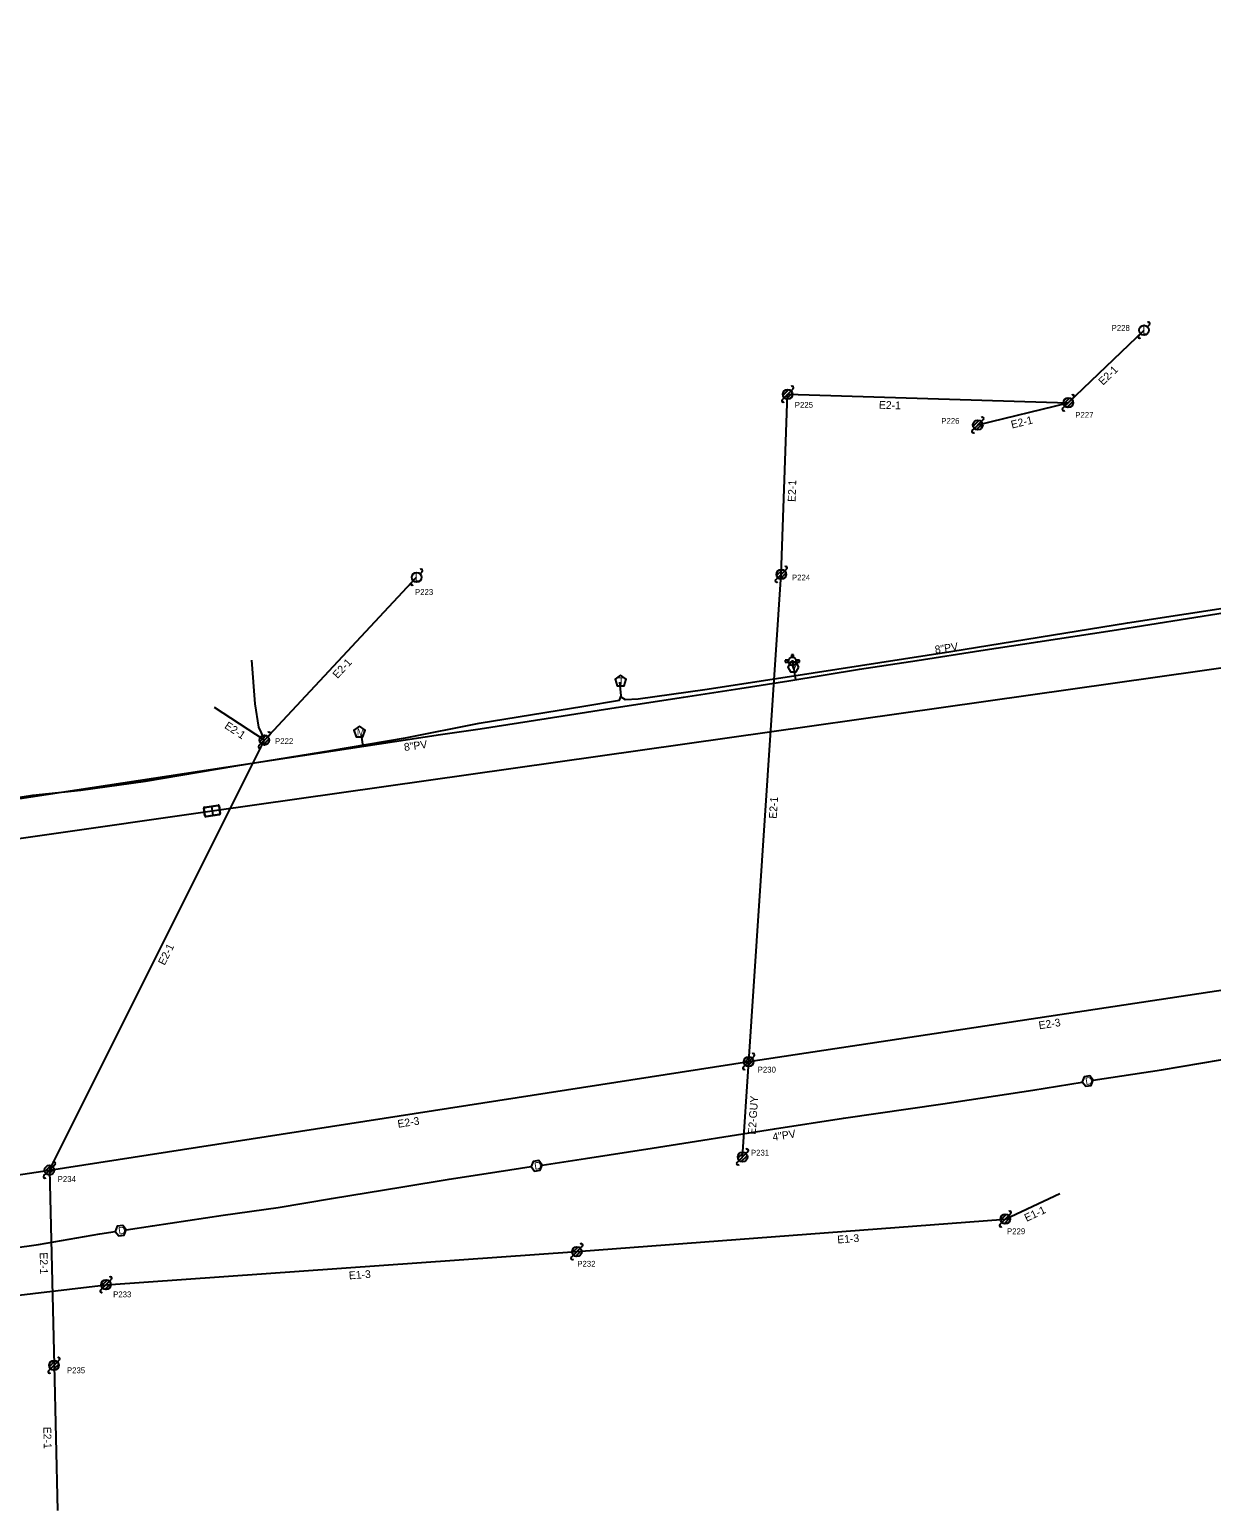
# Model space of a CAD drawing. Extents: x 1614474 to 1865144, y 1098877 to 1212550.
# Drawn here: x 1776816 to 1777423, y 1179838 to 1180599 of the extents above; entities that cross this region are included whole.
import ezdxf

# ---------------------------------------------------------------- set-up
doc = ezdxf.new("R2010")
doc.units = 0
for name, color, linetype in [('BFUSER_DUCTENCLOSURE', 7, 'Continuous'), ('BFUSER_FIBERSPAN', 7, 'Continuous'), ('RD_EX_SU_Elec', 7, 'Continuous'), ('RD_EX_SU_H2O', 7, 'Continuous'), ('RD_EX_SU_Ovhd', 7, 'Continuous'), ('RD_EX_SU_Pole', 7, 'Continuous'), ('RD_EX_SU_Telecom', 7, 'Continuous'), ('RD_EX_SU_TX_H2O', 7, 'Continuous'), ('RD_EX_SU_TX_Pole', 7, 'Continuous')]:
    doc.layers.add(name, color=color, linetype=linetype)

# ---------------------------------------------------------------- blocks, each defined once
blk = doc.blocks.new('SUE_PP')
at = {"layer": 'RD_EX_SU_Pole'}
for p, q in [((-2.41, -0.65), (0.65, 2.41)), ((-1.77, -1.77), (1.77, 1.77)), ((-0.65, -2.41), (2.41, 0.65)), ((1.77, 1.77), (2.83, 2.83)), ((-2.83, -2.83), (-1.77, -1.77))]:
    blk.add_line(p, q, dxfattribs=at)
blk.add_circle((0, 0), 2.5, dxfattribs=at)
for centre, start, end in [((2.3, 3.36), 315, 135), ((-2.3, -3.36), 135, 315)]:
    blk.add_arc(centre, 0.75, start, end, dxfattribs=at)
blk = doc.blocks.new('SUE_WM')
at = {"layer": 'RD_EX_SU_H2O'}
blk.add_lwpolyline([(0, 3.05), (-2.9, 0.94), (-1.79, -2.47), (1.79, -2.47), (2.9, 0.94)], close=True, dxfattribs=at)
blk.add_text('M', height=3.75, dxfattribs=at).set_placement((-1.43, -1.88))
blk = doc.blocks.new('SUE_TPP')
at = {"layer": 'RD_EX_SU_Telecom'}
blk.add_lwpolyline([(0, 3), (-2.85, 0.93), (-1.76, -2.43), (1.76, -2.43), (2.85, 0.93)], close=True, dxfattribs=at)
blk.add_text('T', height=3.75, dxfattribs=at).set_placement((-1.25, -1.88))
blk = doc.blocks.new('SUE_WFH')
at = {"layer": 'RD_EX_SU_H2O'}
for p, q in [((-2.01, 0.6), (-3.65, 0.6)), ((-3.65, 0.6), (-3.65, -0.45)), ((-0.48, 3.38), (-0.48, 2.04)), ((0.57, 3.38), (-0.48, 3.38)), ((0.57, 2.02), (0.57, 3.38)), ((3.7, 0.6), (2.01, 0.6)), ((3.7, -0.45), (3.7, 0.6)), ((-3.65, -0.45), (-2.05, -0.45)), ((2.05, -0.45), (3.7, -0.45))]:
    blk.add_line(p, q, dxfattribs=at)
for radius in [2.1, 0.263]:
    blk.add_circle((0, 0), radius, dxfattribs=at)
for start, end in [(163.3387, 192.31502), (74.24552, 103.21276), (347.68498, 16.6613)]:
    blk.add_arc((0, 0), 2.1, start, end, dxfattribs=at)
blk = doc.blocks.new('SUE_WV')
at = {"layer": 'RD_EX_SU_H2O'}
blk.add_lwpolyline([(2.89, 0), (1.44, 2.5), (-1.44, 2.5), (-2.89, 0), (-1.44, -2.5), (1.44, -2.5)], close=True, dxfattribs=at)
blk.add_text('V', height=3.75, dxfattribs=at).set_placement((-1.43, -1.88))

msp = doc.modelspace()

# ---------------------------------------------------------------- linework, layer by layer
at = {"layer": 'BFUSER_DUCTENCLOSURE'}
msp.add_line((1776909.03, 1180199.71), (1776909.71, 1180195.25), dxfattribs=at)
for points in [[(1776905.71, 1180194.91), (1776905.12, 1180198.86)], [(1776905.92, 1180195.08), (1776905.37, 1180198.75)], [(1776905.54, 1180199.43), (1776912.46, 1180200.47)], [(1776905.71, 1180199.21), (1776912.36, 1180200.21)], [(1776912.82, 1180199.88), (1776913.37, 1180196.21)], [(1776913.03, 1180200.05), (1776913.62, 1180196.1)], [(1776913.2, 1180195.53), (1776906.28, 1180194.49)], [(1776906.38, 1180194.75), (1776913.04, 1180195.75)]]:
    msp.add_lwpolyline(points, dxfattribs=at)
for centre, radius, start, end in [((1776905.61, 1180198.94), 0.5, 98.58603, 188.58603), ((1776905.76, 1180198.81), 0.4, 98.58603, 188.58603), ((1776912.42, 1180199.82), 0.4, 8.58603, 98.58603), ((1776912.53, 1180199.98), 0.5, 8.58603, 98.58603), ((1776906.21, 1180194.98), 0.5, 188.58603, 278.58603), ((1776906.32, 1180195.14), 0.4, 188.58603, 278.58603), ((1776912.98, 1180196.15), 0.4, 278.58603, 8.58603), ((1776913.13, 1180196.02), 0.5, 278.58603, 8.58603)]:
    msp.add_arc(centre, radius, start, end, dxfattribs=at)
at = {"layer": 'BFUSER_FIBERSPAN'}
msp.add_lwpolyline([(1776119.38, 1180084.52), (1776909.44, 1180197.58), (1777549.89, 1180288.26), (1777793.65, 1180334.21), (1778099.34, 1180399.49), (1778312.74, 1180438.72), (1779456.83, 1180598.99)], dxfattribs=at)
at = {"layer": 'RD_EX_SU_Elec'}
msp.add_lwpolyline([(1776929.59, 1180274.98), (1776931.28, 1180252.44), (1776933.22, 1180240.5), (1776935.91, 1180234.62)], dxfattribs=at)
at = {"layer": 'RD_EX_SU_H2O'}
for p, q in [((1777207.59, 1180274.35), (1777209.13, 1180264.9)), ((1776985.94, 1180236.57), (1776986.85, 1180230.62))]:
    msp.add_line(p, q, dxfattribs=at)
for points in [[(1777026.8, 1180236.7), (1777047.11, 1180239.69), (1777081.14, 1180244.98), (1777117.09, 1180250.63), (1777151.65, 1180255.95), (1777180.57, 1180260.4), (1777205.83, 1180264.36), (1777242.11, 1180270.29), (1777271.65, 1180274.85), (1777304.45, 1180279.84), (1777312.35, 1180281.06), (1777333.7, 1180284.35), (1777371.94, 1180290.22), (1777429.91, 1180299.45)], [(1775079.31, 1179947.86), (1775099.56, 1179951.26), (1775135.1, 1179956.75), (1775200.12, 1179966.22), (1775230.46, 1179971.15), (1775265.28, 1179976.78), (1775296.44, 1179981.42), (1775327.06, 1179986.33), (1775627.47, 1180033.75), (1775910.53, 1180076.48), (1776287.14, 1180136.1), (1776361.29, 1180146.68), (1776578.76, 1180172.75), (1776784.59, 1180199.86), (1777026.8, 1180236.7)], [(1777362.21, 1180059.08), (1777397.23, 1180064.47), (1777457.94, 1180074.6), (1777486.42, 1180080.2), (1777528.78, 1180088.23)], [(1777079.05, 1180015.49), (1777101.24, 1180018.78), (1777135.61, 1180024.13), (1777198.38, 1180034.04), (1777233.81, 1180039.61), (1777284.94, 1180046.97), (1777331.2, 1180053.89), (1777356.52, 1180058.13)], [(1776915, 1179989.77), (1776943.37, 1179993.71), (1776970.73, 1179998.23), (1777007.48, 1180004.24), (1777031.24, 1180008.25), (1777056.85, 1180012.2), (1777073.34, 1180014.65)], [(1776865.29, 1179982.19), (1776878.83, 1179984.31), (1776915, 1179989.77)], [(1776596.66, 1179940.56), (1776649.72, 1179948.66), (1776649.88, 1179948.69), (1776684.14, 1179953.92), (1776696.94, 1179955.9), (1776723.7, 1179960.03), (1776757.53, 1179965.55), (1776792.08, 1179970.65), (1776820.25, 1179974.64), (1776851.76, 1179980.08), (1776859.59, 1179981.3)]]:
    msp.add_lwpolyline(points, dxfattribs=at)
for points in [[(1777362.21, 1180059.08), (1777360.39, 1180061.33), (1777357.54, 1180060.87), (1777356.51, 1180058.17), (1777358.33, 1180055.93), (1777361.18, 1180056.39)], [(1777079.05, 1180015.49), (1777077.25, 1180017.75), (1777074.4, 1180017.33), (1777073.34, 1180014.65), (1777075.13, 1180012.39), (1777077.99, 1180012.81)], [(1776865.29, 1179982.19), (1776863.48, 1179984.44), (1776860.63, 1179983.99), (1776859.59, 1179981.3), (1776861.4, 1179979.05), (1776864.25, 1179979.5)]]:
    msp.add_lwpolyline(points, close=True, dxfattribs=at)
at = {"layer": 'RD_EX_SU_Ovhd'}
for p, q in [((1777349.35, 1180407.22), (1777388.3, 1180444.52)), ((1777201.88, 1180319.03), (1777205.16, 1180411.61)), ((1777205.16, 1180411.61), (1777349.35, 1180407.22)), ((1777302.88, 1180395.81), (1777349.35, 1180407.22)), ((1777185.15, 1180068.65), (1777201.88, 1180319.03)), ((1776936.28, 1180233.84), (1777014.49, 1180317.56)), ((1776936.28, 1180233.84), (1776910.57, 1180250.57)), ((1776825.82, 1180012.85), (1776936.28, 1180233.84)), ((1777185.15, 1180068.65), (1777513.64, 1180118.43)), ((1776825.82, 1180012.85), (1777185.15, 1180068.65)), ((1777181.98, 1180019.63), (1777185.15, 1180068.65)), ((1776443.07, 1179954.72), (1776825.82, 1180012.85)), ((1776825.82, 1180012.85), (1776828.18, 1179912.55)), ((1777317, 1179987.73), (1777345.11, 1180000.88)), ((1777096.85, 1179970.96), (1777317, 1179987.73)), ((1776854.89, 1179953.96), (1777096.85, 1179970.96)), ((1776647.76, 1179929.28), (1776854.89, 1179953.96)), ((1776828.18, 1179912.55), (1776829.93, 1179837.99))]:
    msp.add_line(p, q, dxfattribs=at)
at = {"layer": 'RD_EX_SU_Pole'}
for p, q in [((1777385.47, 1180441.69), (1777386.53, 1180442.75)), ((1777390.07, 1180446.29), (1777391.13, 1180447.35)), ((1777351.12, 1180408.99), (1777352.18, 1180410.05)), ((1777346.52, 1180404.39), (1777347.58, 1180405.45)), ((1777346.94, 1180406.57), (1777350, 1180409.63)), ((1777347.58, 1180405.45), (1777351.12, 1180408.99)), ((1777348.71, 1180404.8), (1777351.77, 1180407.86)), ((1777300.46, 1180395.17), (1777303.53, 1180398.23)), ((1777301.11, 1180394.05), (1777304.65, 1180397.58)), ((1777302.23, 1180393.4), (1777305.29, 1180396.46)), ((1777304.65, 1180397.58), (1777305.71, 1180398.64)), ((1777300.05, 1180392.99), (1777301.11, 1180394.05)), ((1777016.25, 1180319.32), (1777017.31, 1180320.38)), ((1777199.46, 1180318.38), (1777202.52, 1180321.44)), ((1777200.11, 1180317.26), (1777203.64, 1180320.79)), ((1777201.23, 1180316.61), (1777204.29, 1180319.67)), ((1777203.64, 1180320.79), (1777204.7, 1180321.85)), ((1777011.66, 1180314.73), (1777012.72, 1180315.79)), ((1777199.05, 1180316.2), (1777200.11, 1180317.26)), ((1776933.87, 1180233.19), (1776936.93, 1180236.25)), ((1776934.51, 1180232.07), (1776938.05, 1180235.61)), ((1776938.05, 1180235.61), (1776939.11, 1180236.67)), ((1776933.45, 1180231.01), (1776934.51, 1180232.07)), ((1776935.63, 1180231.42), (1776938.7, 1180234.49)), ((1777182.73, 1180068), (1777185.8, 1180071.06)), ((1777183.38, 1180066.88), (1777186.92, 1180070.42)), ((1777184.5, 1180066.23), (1777187.56, 1180069.3)), ((1777186.92, 1180070.42), (1777187.98, 1180071.48)), ((1777182.32, 1180065.82), (1777183.38, 1180066.88)), ((1777179.56, 1180018.98), (1777182.63, 1180022.04)), ((1777183.75, 1180021.4), (1777184.81, 1180022.46)), ((1776823.4, 1180012.21), (1776826.47, 1180015.27)), ((1776824.05, 1180011.08), (1776827.59, 1180014.62)), ((1776827.59, 1180014.62), (1776828.65, 1180015.68)), ((1777179.15, 1180016.8), (1777180.21, 1180017.86)), ((1777180.21, 1180017.86), (1777183.75, 1180021.4)), ((1777181.33, 1180017.21), (1777184.39, 1180020.27)), ((1776822.99, 1180010.02), (1776824.05, 1180011.08)), ((1776825.17, 1180010.44), (1776828.23, 1180013.5)), ((1777314.17, 1179984.91), (1777315.23, 1179985.97)), ((1777314.58, 1179987.09), (1777317.64, 1179990.15)), ((1777315.23, 1179985.97), (1777318.76, 1179989.5)), ((1777316.35, 1179985.32), (1777319.41, 1179988.38)), ((1777318.76, 1179989.5), (1777319.82, 1179990.56)), ((1777094.02, 1179968.13), (1777095.08, 1179969.19)), ((1777094.44, 1179970.31), (1777097.5, 1179973.37)), ((1777095.08, 1179969.19), (1777098.62, 1179972.73)), ((1777096.2, 1179968.54), (1777099.27, 1179971.61)), ((1777098.62, 1179972.73), (1777099.68, 1179973.79)), ((1776852.47, 1179953.31), (1776855.54, 1179956.37)), ((1776853.12, 1179952.19), (1776856.66, 1179955.73)), ((1776854.24, 1179951.54), (1776857.3, 1179954.61)), ((1776856.66, 1179955.73), (1776857.72, 1179956.79)), ((1776852.06, 1179951.13), (1776853.12, 1179952.19)), ((1776829.94, 1179914.32), (1776831, 1179915.38)), ((1776825.35, 1179909.72), (1776826.41, 1179910.78)), ((1776825.76, 1179911.9), (1776828.82, 1179914.96)), ((1776826.41, 1179910.78), (1776829.94, 1179914.32)), ((1776827.53, 1179910.13), (1776830.59, 1179913.2))]:
    msp.add_line(p, q, dxfattribs=at)
for centre in [(1777388.3, 1180444.52), (1777349.35, 1180407.22), (1777302.88, 1180395.81), (1777014.49, 1180317.56), (1777201.88, 1180319.03), (1776936.28, 1180233.84), (1777185.15, 1180068.65), (1777181.98, 1180019.63), (1776825.82, 1180012.85), (1777317, 1179987.73), (1777096.85, 1179970.96), (1776854.89, 1179953.96), (1776828.18, 1179912.55)]:
    msp.add_circle(centre, 2.5, dxfattribs=at)
for centre, start, end in [((1777390.6, 1180447.88), 315, 135), ((1777386, 1180441.16), 135, 315), ((1777351.65, 1180410.58), 315, 135), ((1777347.05, 1180403.86), 135, 315), ((1777305.18, 1180399.17), 315, 135), ((1777300.58, 1180392.45), 135, 315), ((1777016.78, 1180320.92), 315, 135), ((1777204.17, 1180322.38), 315, 135), ((1777012.19, 1180314.2), 135, 315), ((1777199.58, 1180315.67), 135, 315), ((1776938.58, 1180237.2), 315, 135), ((1776933.98, 1180230.48), 135, 315), ((1777187.45, 1180072.01), 315, 135), ((1777182.85, 1180065.29), 135, 315), ((1777184.28, 1180022.99), 315, 135), ((1776828.12, 1180016.21), 315, 135), ((1777179.68, 1180016.27), 135, 315), ((1776823.52, 1180009.49), 135, 315), ((1777319.29, 1179991.09), 315, 135), ((1777314.7, 1179984.38), 135, 315), ((1777099.15, 1179974.32), 315, 135), ((1777094.55, 1179967.6), 135, 315), ((1776857.19, 1179957.32), 315, 135), ((1776852.59, 1179950.6), 135, 315), ((1776830.47, 1179915.91), 315, 135), ((1776825.88, 1179909.19), 135, 315)]:
    msp.add_arc(centre, 0.75, start, end, dxfattribs=at)
at = {"layer": 'RD_EX_SU_Telecom'}
for points in [[(1777119.38, 1180256.14), (1777121.64, 1180254.65), (1777128.39, 1180255.1), (1777162.65, 1180259.86), (1777206.04, 1180266.5), (1777289.09, 1180279.4), (1777379.78, 1180294.05), (1777440.12, 1180303.44), (1777493.73, 1180309.44), (1777507.1, 1180311.61), (1777509.38, 1180314.3), (1777511.03, 1180318.2), (1777509.72, 1180324.02)], [(1776775.88, 1180200.47), (1776777.97, 1180199.57), (1776817.24, 1180205.57), (1776842.01, 1180208.09), (1776875.22, 1180212.72), (1776921.6, 1180220.69), (1776970.49, 1180228.43), (1777008.72, 1180235.02), (1777046.72, 1180242.58), (1777100.46, 1180251.28), (1777118.79, 1180254.3), (1777119.55, 1180256.67), (1777118.94, 1180263.61)]]:
    msp.add_lwpolyline(points, dxfattribs=at)

# ---------------------------------------------------------------- block references
at = {"layer": 'RD_EX_SU_H2O'}
for name, p in [('SUE_WFH', (1777207.59, 1180274.35)), ('SUE_WV', (1777208.07, 1180271.39)), ('SUE_WM', (1776985.14, 1180237.95))]:
    msp.add_blockref(name, p, dxfattribs=at)
at = {"layer": 'RD_EX_SU_Pole'}
msp.add_blockref('SUE_PP', (1777205.16, 1180411.61), dxfattribs=at)
at = {"layer": 'RD_EX_SU_Telecom'}
msp.add_blockref('SUE_TPP', (1777119.34, 1180264.19), dxfattribs=at)

# ---------------------------------------------------------------- texts
at = {"layer": 'RD_EX_SU_H2O'}
for rotation, p in [(9.07908, (1777358.42, 1180056.58)), (8.43397, (1777075.23, 1180013.03)), (8.87141, (1776861.49, 1179979.7))]:
    msp.add_text('D', height=3.75, rotation=rotation, dxfattribs=at).set_placement(p)
at = {"layer": 'RD_EX_SU_Ovhd'}
for s, rotation, p in [('E2-1', 43.76146, (1777367.16, 1180415.97)), ('E2-1', 358.25331, (1777252.01, 1180404.18)), ('E2-1', 13.78761, (1777320.45, 1180393.95)), ('E2-1', 87.96584, (1777209.2, 1180356.2)), ('E2-1', 46.94972, (1776973.81, 1180265.23)), ('E2-1', 326.94138, (1776915.41, 1180240.27)), ('E2-1', 86.17829, (1777199.49, 1180193.35)), ('E2-1', 63.44143, (1776885, 1180117.83)), ('E2-3', 8.61708, (1777334.46, 1180085.21)), ('E2-GUY', 86.29848, (1777188.73, 1180031.03)), ('E2-3', 8.82628, (1777005.01, 1180034.6)), ('E1-1', 25.05321, (1777327.96, 1179986.24)), ('E1-3', 4.35794, (1777230.8, 1179975.15)), ('E2-1', 271.3456, (1776820.81, 1179970.55)), ('E1-3', 4.01887, (1776979.8, 1179956.72)), ('E2-1', 271.3456, (1776822.67, 1179880.92))]:
    msp.add_text(s, height=4, rotation=rotation, dxfattribs=at).set_placement(p)
at = {"layer": 'RD_EX_SU_Pole'}
for p in [(1777387.44, 1180442.52), (1777013.62, 1180315.56)]:
    msp.add_text('L', height=4, dxfattribs=at).set_placement(p)
at = {"layer": 'RD_EX_SU_TX_H2O'}
for s, rotation, p in [('8"PV', 8.65151, (1777281.09, 1180278.31)), ('8"PV', 7.70314, (1777008.29, 1180228.24)), ('4"PV', 8.93151, (1777197.68, 1180027.85))]:
    msp.add_text(s, height=4, rotation=rotation, dxfattribs=at).set_placement(p)
at = {"layer": 'RD_EX_SU_TX_Pole'}
for s, p in [('P228', (1777371.63, 1180444.18)), ('P225', (1777208.82, 1180404.64)), ('P227', (1777352.94, 1180399.49)), ('P226', (1777284.08, 1180396.41)), ('P224', (1777207.35, 1180315.9)), ('P223', (1777013.66, 1180308.47)), ('P222', (1776941.73, 1180231.83)), ('P230', (1777189.76, 1180062.99)), ('P231', (1777186.3, 1180020.3)), ('P234', (1776830.04, 1180006.79)), ('P229', (1777317.88, 1179979.94)), ('P232', (1777097.05, 1179963.23)), ('P233', (1776858.54, 1179947.51)), ('P235', (1776834.79, 1179908.49))]:
    msp.add_text(s, height=3, dxfattribs=at).set_placement(p)

doc.saveas('drawing.dxf')
